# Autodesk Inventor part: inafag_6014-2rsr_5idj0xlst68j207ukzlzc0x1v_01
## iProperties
Shininess: 64.0
Angle Display Precision: 2
Document Length Units: 11269
Document Angle Units: 11279
Document Time Units: 11290
Document Mass Units: 11283
Document Length Units Precision: 3
Document Angle Units Precision: 2
Compacted: True
Created: 2008-08
Part Number: inafag_6014-2rsr_5idj0xlst68j207ukzlzc0x1v_01
Document SubType Name: Modeling
Designer: tpomodeler
Density: 0.0
Volumn: 0.0
Area: 0.0
PropertySet Name: Model Information
Control State: 0
Master: False
Checked Out: False
Author: tpomodeler
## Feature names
1. inafag_6014-2rsr_5idj0xlst68j207ukzlzc0x1v
